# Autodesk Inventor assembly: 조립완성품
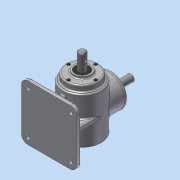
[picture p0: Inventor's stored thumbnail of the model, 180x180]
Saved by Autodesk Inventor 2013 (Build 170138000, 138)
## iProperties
Created: 2015-07
Part Number: 조립완성품
Document SubType Name: Assembly
Designer: dgall
Author: dgall
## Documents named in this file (14)
- C:\Users\dgall\Desktop\450705V1003\조립완성품.iam
- C:\Users\dgall\Desktop\450705V1003\본체.ipt
- C:\Users\dgall\Desktop\450705V1003\메인 축.ipt
- 메인 축.ipt
- C:\Users\dgall\Desktop\450705V1003\베어링 6203.ipt
- C:\Users\dgall\Desktop\450705V1003\커버.ipt
- C:\Users\dgall\Desktop\450705V1003\서브 축.ipt
- 서브 축.ipt
- C:\Users\dgall\Desktop\450705V1003\키 4x4.ipt
- C:\Users\dgall\Desktop\450705V1003\키 5x5.ipt
- C:\Users\dgall\Desktop\450705V1003\메인 베벨기어.ipt
- C:\Users\dgall\Desktop\450705V1003\서브 베벨기어.ipt
- C:\Users\dgall\Desktop\450705V1003\오일실.ipt
- C:\Users\dgall\Desktop\450705V1003\M4.ipt
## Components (8 placed, 1 different names)
1. M4:2
2. M4:3
3. M4:4
4. M4:5
5. M4:1
6. M4:6
7. M4:7
8. M4:8
